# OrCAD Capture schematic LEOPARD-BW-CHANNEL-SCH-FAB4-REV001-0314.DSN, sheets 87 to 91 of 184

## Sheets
87 088_WBG - POWER: size A3; title: WBG - POWER
88 087_WBG - CLOCK: size A3; title: WBG - CLOCK
89 086_WBG - SPI: size A3; title: WBG - SPI
90 085_WBG - GPIO & SMB: size A3; title: WBG - GPIO & SMB
91 084_WBG - SATA: size A3; title: WBG - SATA

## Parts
sheet 083_WBG - DMI & USB
WBG1  WELLSBURG-1-GP-U  [BGA836M25H87]  (sections A,B,C,D,E,F,G,H,I,J,K)
sheet 084_WBG - SATA
C51  SCD1U16V2KX-3GP  [C402H22]
C52  SCD1U16V2KX-3GP  [C402H22]
C755  SCD01U16V2KX-3GP  [C402H22]
C756  SCD01U16V2KX-3GP  [C402H22]
L12  BLM15AG121SN-1GP  [L402H22]
R138  10KR2F-2-GP  [R402H16]
R139  10KR2F-2-GP  [R402H16]
R140  1KR2J-1-GP  [R402H16]
R141  7K5R2F-1-GP  [R402H16]
R203  10KR2F-2-GP  [R402H16]
R222  10KR2F-2-GP  [R402H16]
R230  10KR2F-2-GP  [R402H16]
R292  10KR2F-2-GP  [R402H16]
R296  2KR2F-3-GP  [R402H16]
R297  10KR2F-2-GP  [R402H16]
R298  10KR2F-2-GP  [R402H16]
R302  10KR2F-2-GP  [R402H16]
R322  10KR2F-2-GP  [R402H16]
R323  10KR2F-2-GP  [R402H16]
R353  10KR2F-2-GP  [R402H16]
R371  10KR2F-2-GP  [R402H16]
R522  10KR2F-2-GP  [R402H16]
R590  10KR2F-2-GP  [R402H16]
R611  10KR2F-2-GP  [R402H16]
R780  10KR2F-2-GP  [R402H16]
R831  10KR2F-2-GP  [R402H16]
R837  2KR2F-3-GP  [R402H16]
TP189  TPAD24  [TPAD24]
U43  74VHC1G09DFT2G-GP  [SC70-5H44]
U49  74VHC1G09DFT2G-GP  [SC70-5H44]
sheet 085_WBG - GPIO & SMB
C208  SC15P50V2JN-2-GP  [C402H22]
C209  SC15P50V2JN-2-GP  [C402H22]
R146  10KR2F-2-GP  [R402H16]
R151  10MR3J-L1-GP  [R603H22]
R170  4K7R2F-GP  [R402H16]
R171  4K7R2F-GP  [R402H16]
R172  4K7R2F-GP  [R402H16]
R173  4K7R2F-GP  [R402H16]
R174  10KR2F-2-GP  [R402H16]
R183  10KR2F-2-GP  [R402H16]
R185  2K2R2F-GP  [R402H16]
R186  10KR2F-2-GP  [R402H16]
R194  10KR2F-2-GP  [R402H16]
R196  10KR2F-2-GP  [R402H16]
R198  2K2R2F-GP  [R402H16]
R204  10KR2F-2-GP  [R402H16]
R283  10KR2F-2-GP  [R402H16]
R287  0R2J-2-GP  [R402H16]
R288  0R2J-2-GP  [R402H16]
R299  2K2R2F-GP  [R402H16]
R325  10KR2F-2-GP  [R402H16]
R364  10KR2F-2-GP  [R402H16]
R428  2K2R2F-GP  [R402H16]
R628  0R2J-2-GP  [R402H16]
R802  10KR2F-2-GP  [R402H16]
R853  10KR2F-2-GP  [R402H16]
R919  33R2F-3-GP  [R402H16]
R920  33R2F-3-GP  [R402H16]
R921  33R2F-3-GP  [R402H16]
R922  33R2F-3-GP  [R402H16]
R1046  0R2J-2-GP  [R402H16]
R1113  0R2J-2-GP  [R402H16]
R1114  0R2J-2-GP  [R402H16]
R1115  0R2J-2-GP  [R402H16]
R1585  0R2J-2-GP  [R402H16]
R1595  0R2J-2-GP  [R402H16]
R1597  0R2J-2-GP  [R402H16]
R1598  0R2J-2-GP  [R402H16]
TP192  TPAD24  [TPAD24]
TP193  TPAD24  [TPAD24]
TP199  TPAD24  [TPAD24]
TP234  TPAD24  [TPAD24]
TP235  TPAD24  [TPAD24]
TP236  TPAD24  [TPAD24]
TP334  TPAD24  [TPAD24]
TP335  TPAD24  [TPAD24]
TP336  TPAD24  [TPAD24]
TP337  TPAD24  [TPAD24]
TP338  TPAD24  [TPAD24]
TP339  TPAD24  [TPAD24]
TP340  TPAD24  [TPAD24]
TP341  TPAD24  [TPAD24]
TP343  TPAD24  [TPAD24]
TP351  TPAD24  [TPAD24]
X2  XTAL-32D768KHZ-63-GP  [SMD49-12H34]
sheet 086_WBG - SPI
R144  8K2R2F-1-GP  [R402H16]
R147  10KR2F-2-GP  [R402H16]
R390  10KR2F-2-GP  [R402H16]
TP237  TPAD24  [TPAD24]
sheet 087_WBG - CLOCK
C206  SC12P50V2JN-3GP  [C402H24]
C207  SC12P50V2JN-3GP  [C402H24]
R149  1KR2F-L-GP  [R402H16]
R150  1MR3F-GP  [R603H22]
R274  0R2J-2-GP  [R402H16]
R275  0R2J-2-GP  [R402H16]
R277  0R2J-2-GP  [R402H16]
R278  0R2J-2-GP  [R402H16]
R379  22R2F-1-GP  [R402H16]
R440  22D1R2F-GP  [R402H16]
R959  22D1R2F-GP  [R402H16]
R963  39R2F-GP  [R402H16]
TP327  TPAD24  [TPAD24]
X1  XTAL-25MHZ-96GP  [SMD49-4H56]
sheet 088_WBG - POWER
C210  SC10U6D3V5KX-4GP  [C805H58]
C211  SC1U10V2KX-4-GP  [C402H22]
C212  SC10U6D3V5KX-4GP  [C805H58]
C213  SC1U10V2KX-4-GP  [C402H22]
C214  SC10U6D3V5KX-4GP  [C805H58]
C215  SC10U6D3V5KX-4GP  [C805H58]
C216  SC1U10V2KX-4-GP  [C402H22]
C217  SC1U10V2KX-4-GP  [C402H22]
C218  SC10U6D3V5KX-4GP  [C805H58]
C219  SC1U10V2KX-4-GP  [C402H22]
C220  SC10U6D3V5KX-4GP  [C805H58]
C221  SC1U10V2KX-4-GP  [C402H22]
C662  SCD1U16V2KX-3GP  [C402H22]
L1  IND-10UH-215-GP  [L805H58]
L2  IND-1UH-109-GP  [L805H44]
L3  IND-10UH-215-GP  [L805H58]
L4  IND-1UH-109-GP  [L805H44]
L5  IND-10UH-215-GP  [L805H58]
L6  IND-10UH-215-GP  [L805H58]
L13  BLM15AG121SN-1GP  [L402H22]
R152  D001R2512-GP-U1  [R2512-1U1H36]
R153  D001R2512-GP-U1  [R2512-1U1H36]
R154  0R2J-2-GP  [R402H16]
R155  0R2J-2-GP  [R402H16]
R156  0R2J-2-GP  [R402H16]
R157  0R2J-2-GP  [R402H16]
R158  0R2J-2-GP  [R402H16]
R159  0R2J-2-GP  [R402H16]
R160  0R2J-2-GP  [R402H16]
R161  0R2J-2-GP  [R402H16]
R162  0R2J-2-GP  [R402H16]
R163  0R2J-2-GP  [R402H16]
R165  0R3J-0-U-GP  [R603H22]
R167  0R2J-2-GP  [R402H16]
R168  0R2J-2-GP  [R402H16]
R177  1R2J-GP  [R402H16]
R178  0R2J-2-GP  [R402H16]
TP278  TPAD24  [TPAD24]
TP329  TPAD24  [TPAD24]

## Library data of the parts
WBG1 = WELLSBURG-1-GP-U: IC PCH WELLSBURG FCBGA 836P(SERVER); GREENDFACTOR: R2_C;; POP?: 071.82029.0B0U; Package Type: ASIC2-G4; Part Number: 71.WSBUG.00U; SPEC: http://wpqssvr.wistron.com.tw:7001/wpqs/servlet/COM.qpart.Attachment?PartNumber=71.WSBUG.00U
C51 C52 = SCD1U16V2KX-3GP: CHIP CAP C 0.1U 16V K0402 X7R; CATEGORIES: CAP_1.xV; GREENDFACTOR: R2_SA;HF_SA;G_SA;; MAIN_SOURCE: M; Part Number: 78.10421.2FL; Part Type: SMD-BCG; SPEC: http://wpqssvr.wistron.com.tw:7001/wpqs/servlet/COM.qpart.Attachment?PartNumber=78.10421.2FL
C755 C756 = SCD01U16V2KX-3GP: CHIP CAP0.01U16V K0402 X7R(ROH; Category: PCH; Part Number: 78.10321.2FL; Part Type: SMD-BCG
L12 L13 = BLM15AG121SN-1GP: CHIP BAED BLM15AG121SN1D; GREENDFACTOR: R2_SA;HF_SA;G_SA;; Part Number: 68.00084.921; Part Type: DISCRET-G; SPEC: http://wpqssvr.wistron.com.tw:7001/wpqs/servlet/COM.qpart.Attachment?PartNumber=68.00084.921
R138 R139 R146 R147 R203 R222 R230 = 10KR2F-2-GP: CHIP RES 10K F 1/16W 0402; GREENDFACTOR: R2_SA;HF_SA;G_SA;; Part Number: 64.10025.6DL; Part Type: SMD-RG; SPEC: http://wpqssvr.wistron.com.tw:7001/wpqs/servlet/COM.qpart.Attachment?PartNumber=64.10025.6DL
R140 = 1KR2J-1-GP: CHIP RES 1K J 1/16W 0402; GREENDFACTOR: R2_SA;HF_SA;G_SA;; Part Number: 63.10234.1DL; Part Type: SMD-RG; SPEC: http://wpqssvr.wistron.com.tw:7001/wpqs/servlet/COM.qpart.Attachment?PartNumber=63.10234.1DL
R141 = 7K5R2F-1-GP: CHIP RES 7.5K F 1/16W 0402; Category: PCH; Part Number: 64.75015.6DL; Part Type: SMD-RG
R292 R297 R298 R302 R322 R390 R522 R590 R611 R780 R831 = 10KR2F-2-GP: CHIP RES 10K F 1/16W 0402; GREENDFACTOR: R2_SA;HF_SA;G_SA;; Package Type: SMD-RG; Part Number: 64.10025.6DL; SPEC: http://wpqssvr.wistron.com.tw:7001/wpqs/servlet/COM.qpart.Attachment?PartNumber=64.10025.6DL
R296 R837 = 2KR2F-3-GP: CHIP RES 2K F 1/16W 0402; Category: internal conn; DESCRIPTIO: CHIP RES 2K F 1/16W 0402; GREENDFACTOR: R2_SA;HF_SA;G_SA;; Package Type: SMD-RG; Part Number: 64.20015.6DL; Part Type: SMD-RG; SPEC: http://wpqssvr.wistron.com.tw:7001/wpqs/servlet/COM.qpart.Attachment?PartNumber=64.20015.6DL; VENDORPARTNUMBER: RM04FTN2001 / RTT022001FTH / RR0510S-202-FN / RC0402FR-072KL/WR04X2001FTL
R174 R183 R186 R194 R196 R283 R323 R325 R364 R802 = 10KR2F-2-GP: CHIP RES 10K F 1/16W 0402; Category: PCH; DESCRIPTIO: CHIP RES 10K F 1/16W 0402; GREENDFACTOR: R2_SA;HF_SA;G_SA;; Package Type: SMD-RG; Part Number: 64.10025.6DL; Part Type: SMD-RG; SPEC: http://wpqssvr.wistron.com.tw:7001/wpqs/servlet/COM.qpart.Attachment?PartNumber=64.10025.6DL; VENDORPARTNUMBER: RM04FTN1002 / RTT021002FTH / RR0510S-103-FN / RC0402FR-0710KL/WR04X1002FTL
R353 R371 = 10KR2F-2-GP: CHIP RES 10K F 1/16W 0402; GREENDFACTOR: R2_SA;HF_SA;G_SA;; POP?: NOPOP; Package Type: SMD-RG; Part Number: 64.10025.6DL; SPEC: http://wpqssvr.wistron.com.tw:7001/wpqs/servlet/COM.qpart.Attachment?PartNumber=64.10025.6DL
TP189 TP192 TP193 TP199 TP234-TP237 TP278 TP327 TP329 TP334-TP341 TP343 TP351 = TPAD24: 24 MILS TEST PAD; Category: PCH; Part Number: ZZ.PAD24.001; Part Type: DISCRET2
U43 U49 = 74VHC1G09DFT2G-GP: IC CMOS MC74VHC1G09DFT2G SC-70; CATEGORIES: Logic IC; GREENDFACTOR: R2_SA;HF_SA;G_SA;; MAIN_SOURCE: M; Part Number: 73.01G09.AAH; Part Type: DISCRET-G; SPEC: http://wpqssvr.wistron.com.tw:7001/wpqs/servlet/COM.qpart.Attachment?PartNumber=73.01G09.AAH
C208 C209 = SC15P50V2JN-2-GP: CHIP CAP C 15P 50V J0402 NPO; Category: PCH; DESCRIPTIO: CHIP CAP C 15P 50V J0402 NPO; GREENDFACTOR: R2_SA;HF_SA;G_SA;; MAIN_SOURCE: M; Package Type: SMD-BCG; Part Number: 78.15034.1FL; Part Type: SMD-BCG; SPEC: http://wpqssvr.wistron.com.tw:7001/wpqs/servlet/COM.qpart.Attachment?PartNumber=78.15034.1FL; VENDORPARTNUMBER: 04025A150JAT2A/C1005NPO150JGT/GRM1555C1H150JZ01D/223886915159/CL05C150JB5NNNC/UMK105CH150JV-F/0402N150J500LT
R151 = 10MR3J-L1-GP: CHIP RES 10M J 1/10W 0603; GREENDFACTOR: R2_SA;HF_SA;G_SA;; Package Type: SMD-RG; Part Number: 63.10633.15L; SPEC: http://wpqssvr.wistron.com.tw:7001/wpqs/servlet/COM.qpart.Attachment?PartNumber=63.10633.15L
R170 R171 = 4K7R2F-GP: CHIP RES 4.7K F 1/16W 0402; Category: CPU SIDE BAND; POP?: NOPOP; Part Number: 64.47015.6DL; Part Type: RCL_GP
R172 R173 = 4K7R2F-GP: CHIP RES 4.7K F 1/16W 0402; Category: CPU SIDE BAND; Part Number: 64.47015.6DL; Part Type: RCL_GP
R185 R198 R299 R428 = 2K2R2J-2-GP: CHIP RES 2.2K F 1/16W 0402; Category: BMC; DESCRIPTIO: CHIP RES 2.2K J 1/16W 0402; GREENDFACTOR: R2_SA;HF_SA;G_SA;; Package Type: RCL_GP; Part Number: 64.22015.6DL; Part Type: RCL_GP; SPEC: http://wpqssvr.wistron.com.tw:7001/wpqs/servlet/COM.qpart.Attachment?PartNumber=64.22015.6DL; VENDORPARTNUMBER: RM04FTN2201/RTT022201FTH/RR0510S-222-FN/RC0402FR-072K2L
R204 R853 = 10KR2F-2-GP: CHIP RES 10K F 1/16W 0402; Category: PCH; DESCRIPTIO: CHIP RES 10K F 1/16W 0402; GREENDFACTOR: R2_SA;HF_SA;G_SA;; POP?: NOPOP; Package Type: SMD-RG; Part Number: 64.10025.6DL; Part Type: SMD-RG; SPEC: http://wpqssvr.wistron.com.tw:7001/wpqs/servlet/COM.qpart.Attachment?PartNumber=64.10025.6DL; VENDORPARTNUMBER: RM04FTN1002 / RTT021002FTH / RR0510S-103-FN / RC0402FR-0710KL/WR04X1002FTL
R178 R274 R275 R277 R278 R287 R1046 = 0R2J-2-GP: CHIP RES 0 J 1/16W 0402; Category: PCH; DESCRIPTIO: CHIP RES 0 J 1/16W 0402; GREENDFACTOR: R2_SA;HF_SA;G_SA;; Package Type: SMD-RG; Part Number: 63.R0034.1DL; Part Type: SMD-RG; SPEC: http://wpqssvr.wistron.com.tw:7001/wpqs/servlet/COM.qpart.Attachment?PartNumber=63.R0034.1DL; VENDORPARTNUMBER: RM04JTN0/RTT02000JTH/RR0510X-000-XN/RC0402JR-070RL/WR04X000 PTL
R288 = 0R2J-2-GP: CHIP RES 0 J 1/16W 0402; Category: PCH; DESCRIPTIO: CHIP RES 0 J 1/16W 0402; GREENDFACTOR: R2_SA;HF_SA;G_SA;; POP?: NOPOP; Package Type: SMD-RG; Part Number: 63.R0034.1DL; Part Type: SMD-RG; SPEC: http://wpqssvr.wistron.com.tw:7001/wpqs/servlet/COM.qpart.Attachment?PartNumber=63.R0034.1DL; VENDORPARTNUMBER: RM04JTN0/RTT02000JTH/RR0510X-000-XN/RC0402JR-070RL/WR04X000 PTL
R154 R157 R159 R161 R163 R168 R628 R1113 R1114 = 0R2J-2-GP: CHIP RES 0 J 1/16W 0402; Category: BMC; DESCRIPTIO: CHIP RES 0 J 1/16W 0402; GREENDFACTOR: R2_SA;HF_SA;G_SA;; Package Type: SMD-RG; Part Number: 63.R0034.1DL; Part Type: SMD-RG; SPEC: http://wpqssvr.wistron.com.tw:7001/wpqs/servlet/COM.qpart.Attachment?PartNumber=63.R0034.1DL; VENDORPARTNUMBER: RM04JTN0/RTT02000JTH/RR0510X-000-XN/RC0402JR-070RL/WR04X000 PTL
R919-R922 = 33R2F-3-GP: CHIP RES 33 F 1/16W 0402(ROHS); Category: PCH; DESCRIPTIO: CHIP RES 33 F 1/16W 0402(ROHS); GREENDFACTOR: R2_SA;HF_SA;G_SA;; Package Type: SMD-RG; Part Number: 64.33R05.6DL; Part Type: SMD-RG; SPEC: http://wpqssvr.wistron.com.tw:7001/wpqs/servlet/COM.qpart.Attachment?PartNumber=64.33R05.6DL; VENDORPARTNUMBER: RM04FTN33R0/RTT0233R0FTH/RR0510S-330-FN/RC0402FR-0733RL/WR04X33R0FTL
R155 R156 R158 R160 R162 R167 R1115 = 0R2J-2-GP: CHIP RES 0 J 1/16W 0402; Category: BMC; DESCRIPTIO: CHIP RES 0 J 1/16W 0402; GREENDFACTOR: R2_SA;HF_SA;G_SA;; POP?: NOPOP; Package Type: SMD-RG; Part Number: 63.R0034.1DL; Part Type: SMD-RG; SPEC: http://wpqssvr.wistron.com.tw:7001/wpqs/servlet/COM.qpart.Attachment?PartNumber=63.R0034.1DL; VENDORPARTNUMBER: RM04JTN0/RTT02000JTH/RR0510X-000-XN/RC0402JR-070RL/WR04X000 PTL
R1585 R1595 = 0R2J-2-GP: CHIP RES 0 J 1/16W 0402; Category: Logic; DESCRIPTIO: CHIP RES 0 J 1/16W 0402; GREENDFACTOR: R2_SA;HF_SA;G_SA;; Package Type: SMD-RG; Part Number: 63.R0034.1DL; Part Type: SMD-RG; SPEC: http://wpqssvr.wistron.com.tw:7001/wpqs/servlet/COM.qpart.Attachment?PartNumber=63.R0034.1DL; VENDORPARTNUMBER: RM04JTN0/RTT02000JTH/RR0510X-000-XN/RC0402JR-070RL/WR04X000 PTL
R1597 R1598 = 0R2J-2-GP: CHIP RES 0 J 1/16W 0402; Category: Logic; DESCRIPTIO: CHIP RES 0 J 1/16W 0402; GREENDFACTOR: R2_SA;HF_SA;G_SA;; POP?: NOPOP; Package Type: SMD-RG; Part Number: 63.R0034.1DL; Part Type: SMD-RG; SPEC: http://wpqssvr.wistron.com.tw:7001/wpqs/servlet/COM.qpart.Attachment?PartNumber=63.R0034.1DL; VENDORPARTNUMBER: RM04JTN0/RTT02000JTH/RR0510X-000-XN/RC0402JR-070RL/WR04X000 PTL
X2 = XTAL-32D768KHZ-63-GP: XTAL 32.768KHZ 12.5P 20PPM 9H03200 SMD; GREENDFACTOR: R2_SA;HF_SA;; Package Type: DISCRET-G9; Part Number: 82.30001.F81; SPEC: http://wpqssvr.wistron.com.tw:7001/wpqs/servlet/COM.qpart.Attachment?PartNumber=82.30001.F81
R144 = 8K2R2F-1-GP: CHIP RES 8.2K F 1/16W0402(ROHS; GREENDFACTOR: R2_SA;HF_SA;G_SA;; Package Type: SMD-RG; Part Number: 64.82015.6DL; SPEC: http://wpqssvr.wistron.com.tw:7001/wpqs/servlet/COM.qpart.Attachment?PartNumber=64.82015.6DL
C206 C207 = SC12P50V2JN-3GP: CHIP CAP C 12P 50V J0402 NPO; CATEGORIES: CAP_Small; GREENDFACTOR: R2_SA;HF_SA;G_SA;; MAIN_SOURCE: M; Package Type: SMD-BCG; Part Number: 78.12034.1FL; SPEC: http://wpqssvr.wistron.com.tw:7001/wpqs/servlet/COM.qpart.Attachment?PartNumber=78.12034.1FL
R149 = 1KR2F-L-GP: CHIP RES 1K F 1/16W 0402; GREENDFACTOR: R2_SA;HF_SA;G_SA;; Part Number: 64.10015.L1L; Part Type: SMD-RG2; SPEC: http://wpqssvr.wistron.com.tw:7001/wpqs/servlet/COM.qpart.Attachment?PartNumber=64.10015.L1L
R150 = 1MR3F-GP: CHIP RES 1M F 1/10W 0603(ROHS); Category: PCH; Part Number: 64.10045.55L; Part Type: RCL_GP
R379 = 22R2F-1-GP: CHIP RES 22 F 1/16W 0402(ROHS); Category: Clock; DESCRIPTIO: CHIP RES 22 F 1/16W 0402(ROHS); GREENDFACTOR: R2_SA;HF_SA;G_SA;; Package Type: SMD-RG; Part Number: 64.22R05.6DL; Part Type: SMD-RG; SPEC: http://wpqssvr.wistron.com.tw:7001/wpqs/servlet/COM.qpart.Attachment?PartNumber=64.22R05.6DL; VENDORPARTNUMBER: RM04FTN22R0/RTT0222R0FTH/RR0510S-220-FN/RC0402FR-0722RL
R440 R959 = 22D1R2F-GP: CHIP RES 22.1 F 1/16W 0402; Category: PCH; Part Number: 64.22R15.6DL; Part Type: SMD-RG
R963 = 39R2F-GP: CHIP RES 39 F 1/16W 0402; GREENDFACTOR: R2_SA;HF_SA;G_SA;; POP?: NOPOP; Part Number: 64.39R05.6DL; Part Type: SMD-RG; SPEC: http://wpqssvr.wistron.com.tw:7001/wpqs/servlet/COM.qpart.Attachment?PartNumber=64.39R05.6DL
X1 = XTAL-25MHZ-96GP: XTAL 25MHZ 12P X5H025000FC1H-H; GREENDFACTOR: R2_SA;HF_SA;G_SA;; Package Type: DISCRET-G1; Part Number: 82.30020.791; SPEC: http://wpqssvr.wistron.com.tw:7001/wpqs/servlet/COM.qpart.Attachment?PartNumber=82.30020.791
C210 C212 C214 C215 C218 = SC10U6D3V5KX-4GP: CHIP CAP C 10U 6.3V K0805 X7R; GREENDFACTOR: R2_SA;HF_SA;G_SA;; Part Number: 78.10620.21L; Part Type: SMD-BCG; SPEC: http://wpqssvr.wistron.com.tw:7001/wpqs/servlet/COM.qpart.Attachment?PartNumber=78.10620.21L
C211 C213 C216 C217 C219 C221 = SC1U10V2KX-4-GP: CHIP CAP C 1U 10V K 0402 X6S; GREENDFACTOR: R2_SA;HF_SA;; Part Number: 78.10523.8FL; Part Type: SMD-BCG6; SPEC: http://wpqssvr.wistron.com.tw:7001/wpqs/servlet/COM.qpart.Attachment?PartNumber=78.10523.8FL
C220 = SC10U6D3V5KX-4GP: CHIP CAP C 10U 6.3V K0805 X7R; GREENDFACTOR: R2_SA;HF_SA;G_SA;; POP?: NOPOP; Part Number: 78.10620.21L; Part Type: SMD-BCG; SPEC: http://wpqssvr.wistron.com.tw:7001/wpqs/servlet/COM.qpart.Attachment?PartNumber=78.10620.21L
C662 = SCD1U16V2KX-3GP: CHIP CAP C 0.1U 16V K0402 X7R; Category: CLK GEN; GREENDFACTOR: R_SA;HF_SA;G_SA;; Part Number: 78.10421.2FL; Quotation: 12_14; Type: SMD
L1 L3 L5 = IND-10UH-215-GP: CHIP IND 10UH CL201212T-100M-M; Category: PCH; Part Number: 68.1001D.10E; Part Type: DISCRET-G6
L2 L4 = IND-1UH-109-GP: CHIP IND 1U K CL201209T-1R0K-N; Category: PCH; Part Number: 68.1R020.1N1; Part Type: DISCRET-G6
L6 = IND-10UH-215-GP: CHIP IND 10UH CL201212T-100M-M; Category: PCH; POP?: NOPOP; Part Number: 68.1001D.10E; Part Type: DISCRET-G6
R152 = D001R2512-GP-U1: CHIP RES 0.001 F 1W 2512; GREENDFACTOR: R2_SA;HF_SA;G_SA;; POP?: NOPOP; Package Type: SMD-RG6; Part Number: 64.R0015.77L; SPEC: http://wpqssvr.wistron.com.tw:7001/wpqs/servlet/COM.qpart.Attachment?PartNumber=64.R0015.77L
R153 = D001R2512-GP-U1: CHIP RES 0.001 F 1W 2512; GREENDFACTOR: R2_SA;HF_SA;G_SA;; Package Type: SMD-RG6; Part Number: 64.R0015.77L; SPEC: http://wpqssvr.wistron.com.tw:7001/wpqs/servlet/COM.qpart.Attachment?PartNumber=64.R0015.77L
R165 = 0R3J-0-U-GP: CHIP RES 0 J 1/10W 0603; GREENDFACTOR: R2_SA;HF_SA;G_SA;; Package Type: RCL_GP; Part Number: 63.00000.00L; SPEC: http://wpqssvr.wistron.com.tw:7001/wpqs/servlet/COM.qpart.Attachment?PartNumber=63.00000.00L
R177 = 1R2J-GP: CHIP RES 1 J 1/16W 0402; Category: PCH; Part Number: 63.1R034.1DL; Part Type: RCL_GP

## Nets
GND: C51.2 C52.2 C206.2 C207.2 C208.2 C209.2 C210.2 C211.2 C212.2 C213.2 C214.2 C215.2 C216.2 C217.2 C218.2 C219.2 C220.2 C221.2 C662.2 R140.1 R144.1 R230.2 R390.2 U43.3(GND) U49.3(GND) ; also on sheet 1 2 3 4 5 6 7 8 9 10 11 12 13 14 15 16 17 18 19 20 21 22 23 24 25 26 27 28 29 30 31 32 33 34 35 36 37 38 39 44 46 47 49 50 51 52 53 54 55 56 57 58 59 60 61 62 63 64 65 66 69 70 71 73 74 75 76 78 79 80 81 82 83 84 86 92 93 94 95 96 97 98 99 100 101 102 103 104 105 106 107 108 109 110 111 112 113 114 115 116 117 118 119 128 129 138 139 159 160 161 166 168 169 170 171 172 173 174 175 176 177 180 181 182 183 184
P1V05_DMI_PLL: C212.1 C213.1 L2.2(S) R156.2
P1V05_DSW_INT_CAP: WBG1.N29(DCPSUSBYP) ; also on sheet 173
P1V05_ME_PWR_OPTION: R152.2 R153.2 WBG1.AA26(VCCASW) WBG1.AA27(VCCASW) WBG1.AA29(VCCASW) WBG1.AC26(VCCASW) WBG1.AC27(VCCASW) WBG1.AC29(VCCASW) WBG1.J27(VCCASW) WBG1.T27(VCCASW) WBG1.V26(VCCASW) WBG1.V27(VCCASW) WBG1.V29(VCCASW) WBG1.W29(VCCASW) ; also on sheet 173
P1V5_PCH: L12.2 R157.2 R159.2 R161.2 R163.2 R168.2 WBG1.AP18(VCCVRM) WBG1.AP19(VCCVRM) ; also on sheet 8 45 166 173
P1V05_PCH: L1.1(F) L2.1(F) L3.1(F) L4.1(F) L5.1(F) L6.1(F) R152.1 R155.2 WBG1.AA12(VCCIO) WBG1.AA18(VCCIO) WBG1.AA19(VCCIO) WBG1.AA21(VCC) WBG1.AA23(VCC) WBG1.AA24(VCC) WBG1.AC21(VCC) WBG1.AC23(VCC) WBG1.AC24(VCC) WBG1.AC31(VCC) WBG1.AF21(VCC) WBG1.AF23(VCC) WBG1.AF24(VCC) WBG1.AF26(VCC) WBG1.AF27(VCC) WBG1.AF29(VCC) WBG1.AF31(VCC) WBG1.AG18(VCCIO) WBG1.AG19(VCCIO) WBG1.AG21(VCC) WBG1.AG23(VCC) WBG1.AG24(VCC) WBG1.AG26(VCC) WBG1.AG27(VCC) WBG1.AG29(VCCAUSBPLL) WBG1.AG31(VCC) WBG1.AJ18(VCCIO) WBG1.AJ29(VCCAUSBPLL) WBG1.AL18(VCC) WBG1.AL19(VCC) WBG1.AL21(VCCCLK) WBG1.AL23(VCCCLK) WBG1.AL24(VCC) WBG1.AL26(VCC) WBG1.AL27(VCC) WBG1.AL29(VCC) WBG1.AL31(VCC) WBG1.AL32(VCC) WBG1.AM23(VCCCLK) WBG1.AM24(VCCCLK) WBG1.AM26(VCCCLK) WBG1.AP21(VCCCLK) WBG1.AP23(VCCCLK) WBG1.AP24(VCCCLK) WBG1.AU21(VCCCLK) WBG1.AU23(VCCCLK) WBG1.AW34(VCC) WBG1.N12(VCCIO) WBG1.T18(VCCIO) WBG1.T19(VCCIO) WBG1.T21(VCC) WBG1.T23(VCC) WBG1.V9(VCCIO) WBG1.V18(VCCIO) WBG1.V19(VCCIO) WBG1.V21(VCC) WBG1.V23(VCC) WBG1.W21(VCC) ; also on sheet 10 45 173 175
P1V05_SATA3_PLL: C215.1 C217.1 L3.2(S) R158.2
P1V05_SATA3X_PLL: C220.1 L6.2(S) R167.2
P1V05_STBY_PCH: R153.1 WBG1.V31(VCCASW) WBG1.V32(VCCASW) WBG1.Y35(VCCASW) ; also on sheet 9 45 76
P1V05_SUS_INT_CAP: WBG1.T29(DCPSUS1) ; also on sheet 175
P1V05_USB3_PLL: C214.1 C216.1 L4.2(S) R160.2
P1V5_VCCSST_INT_CAP: WBG1.N27(DCPSST) ; also on sheet 173
P1V05_XCK_DCB: C218.1 C219.1 R154.2 R178.2
P1V05_XCK_VRM: C210.1 C211.1 R162.2 R177.2
P1V05_XCK_VRM_L: L1.2(S) R177.1
P3V3: L13.1 R138.1 R139.1 R165.2 R174.1 R203.2 R222.2 R292.2 R296.1 R297.2 R298.2 R299.1 R302.2 R322.2 R323.1 R353.2 R371.2 R522.1 R780.2 R802.1 R831.2 R837.1 R853.1 WBG1.AJ15(VCCST3_3) WBG1.AP32(VCC3_3) WBG1.AT46(VCCST3_3) WBG1.J25(VCC3_3) WBG1.T24(VCC3_3) WBG1.V24(VCC3_3) ; also on sheet 1 3 8 45 46 48 49 52 54 58 65 74 76 78 83 84 94 95 96 100 101 102 161 166 168 173 174 177 180 181 182 183
P3V3_STBY: C51.1 C52.1 C662.1 R146.1 R147.2 R149.1 R170.1 R171.1 R172.1 R173.1 R183.1 R185.1 R186.1 R194.1 R196.1 R198.2 R204.1 R283.1 R325.1 R364.1 R428.1 R590.1 R611.1 U43.5(VCC) U49.5(VCC) WBG1.AA31(VCCSUS3_3) WBG1.AA32(VCCSUS3_3) WBG1.AC18(VCCSUS3_3) WBG1.AC19(VCCSUS3_3) WBG1.AC32(VCCSUS3_3) WBG1.AF32(VCCSUS3_3) WBG1.AG32(VCCSUS3_3) WBG1.AG38(VCCSUSHDA) WBG1.AJ32(VCCSUS3_3) WBG1.T26(VCCSPI) WBG1.T32(VCCDSW3_3) WBG1.T35(VCCSUS3_3) ; also on sheet 2 3 5 6 8 9 10 11 12 15 16 17 20 21 22 25 26 27 30 31 33 34 35 37 38 39 45 47 49 50 51 52 54 55 59 60 61 62 63 64 65 66 69 70 71 72 73 74 76 79 83 84 92 93 94 95 96 97 98 99 159 161 166 168 173 174 176 177 179 180 182 183 184
P3V_BAT: WBG1.N38(VCCRTC) ; also on sheet 84 173 174 184
PVCCIO: WBG1.AP26(V_PROC_IO) WBG1.L18(V_PROC_IO) ; also on sheet 11 16 26 35 39 46 47 68 97 100 101 102 103 120 129 130 139 160 173 177 179 182
VCCA_DMI_PLL_PCH: R156.1 R157.1 WBG1.AA9(VCCVRM)
VCCA_SATA3_PLL_PCH: R158.1 R159.1 WBG1.N9(VCCVRM)
VCCA_SATA3X_PLL_PCH: C221.1 R167.1 R168.1 WBG1.AP36(VCCVRM)
VCCA_USB3_PLL_PCH: R160.1 R161.1 WBG1.AC15(VCCVRM)
VCCAXCK_DCB_PCH: R154.1 R155.1 WBG1.AU18(VCCCLK)
VCCAXCK_VRM_1P5_PCH: R162.1 R163.1 WBG1.AU15(VCCVRM)
VCCCLK3_3: L13.2 WBG1.AP27(VCCCLK3_3) WBG1.AP29(VCCCLK3_3) WBG1.AU27(VCCCLK3_3) WBG1.AU29(VCCCLK3_3) WBG1.AU32(VCCCLK3_3) WBG1.AV27(VCCCLK3_3) WBG1.AV29(VCCCLK3_3) WBG1.AV32(VCCCLK3_3) ; also on sheet 175
AUD_AZA_SDO: WBG1.AR47(HDA_SDO) ; also on sheet 174
BIOS_FW_GD_N: R325.2 WBG1.G39(GPIO25) ; also on sheet 180
BOARD_ID1_PCH: WBG1.B36(GPIO24/MGPIO0) ; also on sheet 71
BOARD_ID3_PCH: WBG1.M27(GPIO28/MGPIO7) ; also on sheet 71
CLK_14M_PCH: R390.1 WBG1.BA23(REFCLK14IN)
CLK_33K_SUSCLK_PLD: WBG1.J32(SUSCLK/GPIO62) ; also on sheet 50 174
CLK_33M_BMC1_LPC: R959.2 ; also on sheet 74
CLK_33M_CPLD_LPC: R963.2 ; also on sheet 52
CLK_33M_PCH: R379.2 ; also on sheet 166
CLK_33M_PCH_BMC_LPC_R: R959.1 WBG1.BF22(CLKOUT_PCI2)
CLK_33M_PCH_CPLD_R: R963.1 WBG1.BF24(CLKOUT_PCI4)
CLK_33M_PCH_TPM_CONN_R: R440.1 WBG1.BH24(CLKOUT_PCI3)
CLK_33M_PCH_TPM_R: R379.1 WBG1.BH22(CLKOUT_PCI0)
CLK_33M_TPM_CONN: R440.2 ; also on sheet 78
CLK_100M_DB1900_DN: R275.2 ; also on sheet 58
CLK_100M_DB1900_DP: R274.2 ; also on sheet 58
CLK_100M_PCH_CPY_DN: WBG1.P2(CLKIN_CPY_N) ; also on sheet 56
CLK_100M_PCH_CPY_DP: WBG1.P4(CLKIN_CPY_P) ; also on sheet 56
CLK_100M_PCH_DB1900_R_DN: R275.1 WBG1.AY4(CLKOUT_DMI_N1)
CLK_100M_PCH_DB1900_R_DP: R274.1 WBG1.AY2(CLKOUT_DMI_P1)
CLK_100M_PCH_XDP_DN: R278.1 WBG1.BC16(CLKOUT_ITPXDP_N)
CLK_100M_PCH_XDP_DP: R277.1 WBG1.BD16(CLKOUT_ITPXDP_P)
CLK_100M_XDP_DN: R278.2 ; also on sheet 47
CLK_100M_XDP_DP: R277.2 ; also on sheet 47
COM1_RI_BMC: R1046.2 ; also on sheet 180
DB_PRESENT_N: R628.2 ; also on sheet 69
DB_PRESENT_R_N: R174.2 R628.1 WBG1.A25(BMBUSY#/GPIO0)
FILTER_P1V05_XCK_DCB: L5.2(S) R178.1
FM_BIOS_POST_CMPLT_N: R283.2 WBG1.D34(GPIO46) ; also on sheet 74
FM_BIOS_RCVR_BOOT_N: WBG1.G27(GPIO45) ; also on sheet 84
FM_BMC_PCH_SCI_LPC_N: R194.2 WBG1.AM48(GPIO13) ; also on sheet 74
FM_BMC_PWRBTN_OUT_N: WBG1.N43(PWRBTN#) ; also on sheet 168
FM_GPIO_ALERT_BUF_EN: R230.1 WBG1.V36(TACH7/GPIO71) ; also on sheet 52
FM_LA_TRIGGER_N_PLD_TDO: WBG1.J29(GPIO26) ; also on sheet 84
FM_LVC1_THERMTRIP_N: WBG1.A13(THRMTRIP#) ; also on sheet 182
FM_ME_CMM_N: R1115.2 ; also on sheet 84
FM_ME_RCVR_N: WBG1.C39(GPIO57/MGPIO5) ; also on sheet 84
FM_MEZZ_PRSNT_N: R802.2 WBG1.J21(GPIO32) ; also on sheet 95
FM_NMI_EVENT_N_NOA_CLK2: WBG1.F11(GPIO35/NMI#) ; also on sheet 180
FM_PASSWORD_CLEAR_N: WBG1.N44(INTRUDER#) ; also on sheet 84
FM_PCH_BMC_THERMTRIP_N: R1114.2 ; also on sheet 52
FM_PCH_BMC_THERMTRIP_R_N: R198.1 R1114.1 R1115.1 WBG1.L44(SML1ALERT#/PCHHOT#/GPIO74/MGPIO8)
FM_PCH_LAN1_DISABLE_N: WBG1.G32(GPIO44) ; also on sheet 64 174
FM_PCH_LDRQ_N: TP343.1 WBG1.AD46(LDRQ0#)
FM_PCH_PRSNT_CO_N: R147.1 WBG1.D48(CGC_DUT_DETECT#) ; also on sheet 51
FM_PCIE_SLOT_CPRSNT2_N: WBG1.V44(TACH2/GPIO6) ; also on sheet 94
FM_PCIE_SLOT_CPRSNT3_N: WBG1.AW23(CLKOUTFLEX0/GPIO64) ; also on sheet 94
FM_PCIE_SLOT_CPRSNT4_N: WBG1.BC23(CLKOUTFLEX3/GPIO67) ; also on sheet 94
FM_PCIE_SLOT_CPRSNT5_N: WBG1.BJ17(CLKOUTFLEX2/GPIO66) ; also on sheet 94
FM_PCIE_SLOT_CPRSNT6_N: WBG1.BD23(CLKOUTFLEX1/GPIO65) ; also on sheet 94
FM_QPI_SLOW_MODE_N: WBG1.AJ49(GPIO33) ; also on sheet 84
FM_SLPA_N: WBG1.E48(SLP_A#) ; also on sheet 9
FM_SLPS3_N: WBG1.B46(SLP_S3#) ; also on sheet 51 52 59 74
FM_SLPS4_N: WBG1.J49(SLP_S4#) ; also on sheet 51 74
FM_SMI_ACTIVE_N: WBG1.M23(GPIO20/SMI#) ; also on sheet 74
FM_USB3_P0_EN_N: R353.1 WBG1.V41(TACH6/GPIO70) ; also on sheet 176
FM_USB3_P1_EN_N: R371.1 WBG1.T40(TACH0/GPIO17) ; also on sheet 176
H_PM_SYNC_G: WBG1.J18(PM_SYNC) ; also on sheet 129 139
HDD_LED_SATA_ACT_N: U43.4(OUT_Y) U49.4(OUT_Y) ; also on sheet 65
IRQ_BMC_PCH_NMI_NOA1_CLK_MUX: WBG1.C41(GPIO8) ; also on sheet 174
IRQ_IBMC_PCH_SMI_LPC_N: R364.2 WBG1.L47(LAN_PHY_PWR_CTRL/GPIO12) ; also on sheet 177
IRQ_LVC3_WAKE_N: R149.2 WBG1.F44(WAKE#) ; also on sheet 64 74 81 83 94 95 168
IRQ_SERIAL: R323.2 WBG1.L21(SERIRQ) ; also on sheet 52 74 78
IRQ_SML0_ALERT_N: R1113.2 ; also on sheet 74
IRQ_SML0_ALERT_R_N: R1113.1 WBG1.D42(SML0ALERT#/GPIO60/MGPIO4)
IRQ_SML1_PMBUS_ALERT_N: R204.2 WBG1.K48(GPIO31/MGPIO2) ; also on sheet 52 54 60 74
LED_SATA_ACT_N: R222.1 U49.1(IN_B) WBG1.J7(SATALED#)
LED_SSATA_ACT_N: R203.1 U49.2(IN_A) WBG1.BH34(SSATALED#)
LPC_FRAME_N: WBG1.AA41(LFRAME#) ; also on sheet 52 74 78
LPC_LAD0: R922.1 ; also on sheet 74 78
LPC_LAD1: R921.1 ; also on sheet 74 78
LPC_LAD2: R920.1 ; also on sheet 74 78
LPC_LAD3: R919.1 ; also on sheet 74 78
MSATA_LED_N: R590.2 U43.1(IN_B) ; also on sheet 81
MSATA_SSD_PRSNT_N: R522.2 WBG1.T36(TACH4/GPIO68) ; also on sheet 81
NGFF_LED_N: R611.2 U43.2(IN_A) ; also on sheet 83
NOA_8_GP21_PD: WBG1.D4(SATA0GP/GPIO21) ; also on sheet 174
NOA_9_RST_PCIE_PCH_N: WBG1.B24(SATA1GP/GPIO19) ; also on sheet 48 49
NOA_10_FM_BIOS_ADV_FUNCTIONS: WBG1.B5(SATA2GP/GPIO36) ; also on sheet 174
NOA_12_FM_NM_THROTTLE_N: WBG1.A9(SATA4GP/GPIO16/MGPIO9) ; also on sheet 183
NOA_13_FM_CPU_PROCHOT_N: WBG1.B28(SATA5GP/GPIO49/MGPIO10) ; also on sheet 48
NOA_14_GP18_TP: WBG1.G21(GPIO18) ; also on sheet 48
PCH_DIMM_RDY: R322.1 WBG1.T38(TACH3/GPIO7) ; also on sheet 52
PCH_LPC_LAD0: R922.2 WBG1.AA40(LAD0)
PCH_LPC_LAD1: R921.2 WBG1.AA38(LAD1)
PCH_LPC_LAD2: R920.2 WBG1.AC47(LAD2)
PCH_LPC_LAD3: R919.2 WBG1.AA36(LAD3)
PCH_VCCPFUSE_3P3_R: R165.1 WBG1.T31(VCC3_3) ; also on sheet 173
PCH_XCLK_BIASREF: L12.1 R141.2 WBG1.AW11(ICLK_IREF)
PCH_XCLK_BIASREF_R: R141.1 WBG1.BA11(DIFFCLK_BIASREF)
PD_PCH_SSTCTL: R140.2 WBG1.C43(SST)
PD_PGDMON: WBG1.AH46(NCTF/TP#AH46) ; also on sheet 174
PD_TD_IREF: R144.2 WBG1.BC6(TD_IREF)
PECI_PCH: WBG1.A21(PECI) ; also on sheet 68
POWER_FAIL: WBG1.G11(SATA3GP/GPIO37) ; also on sheet 54 60
PU_GPIO15_SSB: R428.2 WBG1.B34(GPIO15)
PU_PCH_DSWODVREN: WBG1.N40(DSWVRMEN) ; also on sheet 174
PU_PCH_GP73_PLD_TMS: R183.2 WBG1.F29(GPIO73)
PU_PCH_GPIO1: R831.1 WBG1.T41(TACH1/GPIO1)
PU_PCH_GPIO34: R299.2 WBG1.F21(GPIO34)
PU_PCH_GPIO72: R186.2 WBG1.G47(GPIO72)
PU_PCH_INTVRMEN: WBG1.N47(INTVRMEN) ; also on sheet 174
PU_PCH_RCIN_N: R139.2 WBG1.C25(RCIN#)
PU_PCH_RI_R_N: R185.2 R1046.1 WBG1.J39(RI#)
PU_PCH_RSVD_6: R138.2 WBG1.B26(RESERVED#B26)
PU_SATAX0GP: R292.1 WBG1.AW32(SSATA0GP)
PU_SATAX1GP: R302.1 WBG1.BF36(SSATA1GP)
PU_SATAX2GP: R298.1 WBG1.BH36(SSATA2GP)
PU_SATAX3GP: R297.1 WBG1.BF38(SSATA3GP)
PU_SGPIO_SATA_DATAOUT1: R837.2 WBG1.D6(SDATAOUT1/GPIO48)
PU_SUSACK_N: R146.2 WBG1.A41(SUSACK#)
PWRGD_CPUPWRGD_1V: WBG1.F6(PROCPWRGD) ; also on sheet 182
PWRGD_DRAMPWRGD_CO: R196.2 WBG1.B45(DRAMPWROK) ; also on sheet 97
PWRGD_P1V05_PCH_STBY_DLY: R287.2 ; also on sheet 51 174
PWRGD_PCH_APWROK: R287.1 R288.2 WBG1.G29(APWROK)
PWRGD_PCH_PWROK: R288.1 WBG1.M48(PCH_PWROK) ; also on sheet 51 52 174
PWRGD_SYS_PWROK: WBG1.D30(SYS_PWROK) ; also on sheet 51 52 174
REVISION_ID0_PCH: WBG1.L29(GPIO27/MGPIO6) ; also on sheet 71
REVISION_ID1_PCH: WBG1.H48(SLP_WLAN#/GPIO29/MGPIO3) ; also on sheet 71
REVISION_ID2_PCH: WBG1.F43(SUSWARN#/GPIO30/MGPIO1) ; also on sheet 71
ROW_EN: R853.2 WBG1.AA35(LDRQ1#/GPIO23) ; also on sheet 168
RST_PCH_RSTBTN_N: WBG1.D26(SYS_RESET#) ; also on sheet 182
RST_PCIE_CPU_N: WBG1.F39(SMBALERT#/GPIO11) ; also on sheet 51
RST_PLTRST_N: WBG1.G38(PLTRST#) ; also on sheet 51 100 174 177
RST_RSMRST_PCH_N: WBG1.N41(DPWROK) WBG1.T44(RSMRST#) ; also on sheet 182
RST_RTCRST_N: WBG1.P48(RTCRST#) ; also on sheet 84
RST_SRTCRST_N: WBG1.M46(SRTCRST#) ; also on sheet 84
SATA0_TX_C_DN: WBG1.B12(SATA_TXN0) ; also on sheet 1
SATA0_TX_C_DP: WBG1.D12(SATA_TXP0) ; also on sheet 1
SATA1_TX_C_DN: WBG1.D14(SATA_TXN1) ; also on sheet 1
SATA1_TX_C_DP: WBG1.B14(SATA_TXP1) ; also on sheet 1
SATA2_TX_C_DN: WBG1.B16(SATA_TXN2) ; also on sheet 1
SATA2_TX_C_DP: WBG1.D16(SATA_TXP2) ; also on sheet 1
SATA3_TX_C_DN: WBG1.B18(SATA_TXN3) ; also on sheet 1
SATA3_TX_C_DP: WBG1.D18(SATA_TXP3) ; also on sheet 1
SATA4_TX_C_DN: C756.2 WBG1.B8(SATA_TXN4/PETN1)
SATA4_TX_C_DP: C755.2 WBG1.D8(SATA_TXP4/PETP1)
SATA4_TX_DN: C756.1 ; also on sheet 81 83
SATA4_TX_DP: C755.1 ; also on sheet 81 83
SATA5_TX_C_DN: WBG1.D10(SATA_TXN5/PETN2) ; also on sheet 82
SATA5_TX_C_DP: WBG1.B10(SATA_TXP5/PETP2) ; also on sheet 82
SATA6G_P0_RX_DN: WBG1.G12(SATA_RXN0) ; also on sheet 1
SATA6G_P0_RX_DP: WBG1.F12(SATA_RXP0) ; also on sheet 1
SATA6G_P1_RX_DN: WBG1.J16(SATA_RXN1) ; also on sheet 1
SATA6G_P1_RX_DP: WBG1.L16(SATA_RXP1) ; also on sheet 1
SATA6G_P2_RX_DN: WBG1.N18(SATA_RXN2) ; also on sheet 1
SATA6G_P2_RX_DP: WBG1.M18(SATA_RXP2) ; also on sheet 1
SATA6G_P3_RX_DN: WBG1.F18(SATA_RXN3) ; also on sheet 1
SATA6G_P3_RX_DP: WBG1.G18(SATA_RXP3) ; also on sheet 1
SATA6G_P4_RX_DN: WBG1.F7(SATA_RXN4/PERP1) ; also on sheet 81 83
SATA6G_P4_RX_DP: WBG1.G7(SATA_RXP4/PERN1) ; also on sheet 81 83
SATA6G_P5_RX_DN: WBG1.J11(SATA_RXN5/PERP2) ; also on sheet 82
SATA6G_P5_RX_DP: WBG1.L11(SATA_RXP5/PERN2) ; also on sheet 82
SGPIO_SATA_CLOCK: WBG1.J12(SCLOCK/GPIO22) ; also on sheet 1
SGPIO_SATA_DATAOUT0: WBG1.M21(SDATAOUT0/GPIO39) ; also on sheet 1
SGPIO_SATA_LOAD: WBG1.G6(SLOAD/GPIO38) ; also on sheet 1
SGPIO_SSATA_CLOCK: WBG1.BD29(SSCLOCK) ; also on sheet 1
SGPIO_SSATA_DATAOUT0: WBG1.BH38(SSDATAOUT0) ; also on sheet 1
SGPIO_SSATA_LOAD: WBG1.BC29(SSLOAD) ; also on sheet 1
SMB_CLK: R170.2 R1585.2 WBG1.L39(SMBCLK)
SMB_DATA: R171.2 R1595.2 WBG1.B40(SMBDATA)
SMB_HOST_STBY_LVC3_CLK: R1585.1 ; also on sheet 47 55 74 77 161
SMB_HOST_STBY_LVC3_DATA: R1595.1 ; also on sheet 47 55 74 77 161
SMB_PMBUS_BMC_STBY_LVC3_CLK: R1597.1 ; also on sheet 60 74 77 162
SMB_PMBUS_BMC_STBY_LVC3_DATA: R1598.1 ; also on sheet 60 74 77 162
SMB_SMLINK0_STBY_LVC3_CLK: WBG1.J38(SML0CLK) ; also on sheet 74 77
SMB_SMLINK0_STBY_LVC3_DATA: WBG1.F38(SML0DATA) ; also on sheet 74 77
SML1_CLK: R172.2 R1597.2 WBG1.L38(SML1CLK/GPIO58/MGPIO11)
SML1_DATA: R173.2 R1598.2 WBG1.N36(SML1DATA/GPIO75/MGPIO12)
SPEAKER_PCH: WBG1.C27(SPKR) ; also on sheet 65 174
SPI_PCH_CLK_R: WBG1.C31(SPI_CLK) ; also on sheet 79
SPI_PCH_CS0_R_N: WBG1.G23(SPI_CS0#) ; also on sheet 79
SPI_PCH_IO2_R: WBG1.L27(SPI_IO2) ; also on sheet 79
SPI_PCH_IO3_R: WBG1.C29(SPI_IO3) ; also on sheet 79
SPI_PCH_MISO_R: WBG1.N23(SPI_MISO) ; also on sheet 79
SPI_PCH_MOSI_R: WBG1.B30(SPI_MOSI) ; also on sheet 79
SSATA6G_0_RX_C_DN: WBG1.AU44(SSATA_RXN0) ; also on sheet 1
SSATA6G_0_RX_C_DP: WBG1.AU43(SSATA_RXP0) ; also on sheet 1
SSATA6G_0_TX_C_DN: WBG1.BB46(SSATA_TXN0) ; also on sheet 1
SSATA6G_0_TX_C_DP: WBG1.BB48(SSATA_TXP0) ; also on sheet 1
SSATA6G_1_RX_C_DN: WBG1.AW44(SSATA_RXN1) ; also on sheet 1
SSATA6G_1_RX_C_DP: WBG1.BA44(SSATA_RXP1) ; also on sheet 1
SSATA6G_1_TX_C_DN: WBG1.BE48(SSATA_TXN1) ; also on sheet 1
SSATA6G_1_TX_C_DP: WBG1.BD46(SSATA_TXP1) ; also on sheet 1
SSATA6G_2_RX_C_DN: WBG1.BD43(SSATA_RXN2) ; also on sheet 1
SSATA6G_2_RX_C_DP: WBG1.BC43(SSATA_RXP2) ; also on sheet 1
SSATA6G_2_TX_C_DN: WBG1.BH42(SSATA_TXN2) ; also on sheet 1
SSATA6G_2_TX_C_DP: WBG1.BF42(SSATA_TXP2) ; also on sheet 1
SSATA6G_3_RX_C_DN: WBG1.BA39(SSATA_RXN3) ; also on sheet 1
SSATA6G_3_RX_C_DP: WBG1.AW39(SSATA_RXP3) ; also on sheet 1
SSATA6G_3_TX_C_DN: WBG1.BH40(SSATA_TXN3) ; also on sheet 1
SSATA6G_3_TX_C_DP: WBG1.BF40(SSATA_TXP3) ; also on sheet 1
SUS_STAT_N_PLD_TDI: TP193.1 WBG1.C37(GPIO61)
TP_CLKOUT_PCI_1: TP327.1 WBG1.BJ21(CLKOUT_PCI1)
TP_PCH_HDA_BCLK: TP340.1 WBG1.AK48(HDA_BCLK)
TP_PCH_HDA_RST_N: TP341.1 WBG1.AM46(HDA_RST#)
TP_PCH_HDA_SDI0: TP339.1 WBG1.AJ47(HDA_SDI0)
TP_PCH_HDA_SDI1: TP338.1 WBG1.AL47(HDA_SDI1)
TP_PCH_HDA_SDI2: TP337.1 WBG1.AN49(HDA_SDI2)
TP_PCH_HDA_SDI3: TP336.1 WBG1.AN47(HDA_SDI3)
TP_PCH_HDA_SYNC: TP351.1 WBG1.AP48(HDA_SYNC)
TP_PCH_PMTEST_RST: TP236.1 WBG1.A33(NCTF/TP#A33)
TP_PCH_RSVD_4: TP192.1 WBG1.F34(RESERVED#F34)
TP_PM_SYNC2: TP189.1 WBG1.BJ27(PM_SYNC2)
TP_RST_PLTRST_CPU_1V05_N: TP237.1 WBG1.A17(PLTRST_PROC#)
TP_SGPIO_SATAX_DATAOUT1: R296.2 WBG1.BF34(SSDATAOUT1)
TP_SLP_LAN_N: TP235.1 WBG1.J47(SLP_LAN#)
TP_SLPS5_N: TP199.1 WBG1.D38(SLP_S5#/GPIO63)
TP_SLPSUS_N_BUFF: TP234.1 WBG1.H46(SLP_SUS#)
TP_SPI_CS1: TP335.1 WBG1.L23(SPI_CS1#)
TP_SPI_CS2: TP334.1 WBG1.N21(SPI_CS2#)
TP_VCCDUSBSUS_1P05: TP278.1 WBG1.AC35(DCPSUS2)
TP_VCCUSB3SUS_1P05: TP329.1 WBG1.AF18(DCPSUS3) WBG1.AF19(DCPSUS3)
TPM_PRSNT_N: R780.1 WBG1.T43(TACH5/GPIO69) ; also on sheet 78
XDP_PCH_TCK0: WBG1.G34(JTAG_TCK) ; also on sheet 49
XDP_PCH_TDI: WBG1.F32(JTAG_TDI) ; also on sheet 49
XDP_PCH_TDO: WBG1.C33(JTAG_TDO) ; also on sheet 49
XDP_PCH_TMS: WBG1.B32(JTAG_TMS) ; also on sheet 49
XTAL_PCH_25M_IN: C206.1 R150.1 WBG1.BA12(XTAL25_IN) X1.1
XTAL_PCH_25M_OUT: C207.1 R150.2 WBG1.AW12(XTAL25_OUT) X1.2
XTAL_PCH_RTC1: C209.1 R151.1 WBG1.T46(RTCX1) X2.2
XTAL_PCH_RTC2: C208.1 R151.2 WBG1.R47(RTCX2) X2.1

Not connected (* = marked no-connect by the designer): WBG1 AG9(NCTF/TP#AG9)* AG10(NCTF/TP#AG10)* AW6(RESERVED#AW6)* AW7(NCTF/TP#AW7)* B4(NC_DUT_DETECT_1)* BA6(RESERVED#BA6)* BA7(NCTF/TP#BA7)* BA18(CLKOUT_GPB_PCIE_P1)* BA34(NCTF/TP#BA34)* BB2(CLKOUT_PCIE_N6)* BB4(CLKOUT_PCIE_P6)* BC7(NCTF/TP#BC7)* BC11(CLKOUT_PCIE_N7)* BC18(CLKOUT_GPB_PCIE_N1)* BC21(CLKOUT_PCIE_P0)* BC34(NCTF/TP#BC34)* BD7(NCTF/TP#BD7)* BD11(CLKOUT_PCIE_P7)* BD21(CLKOUT_PCIE_N0)* BF2(NC_DUT_DETECT_2)* BF6(CLKOUT_PCIE_N5)* BF8(CLKOUT_PCIE_N4)* BF10(CLKOUT_PCIE_N1)* BF12(CLKOUT_GPB_PCIE_N0)* BF14(CLKOUT_PCIE_N3)* BF16(CLKOUT_PCIE_N2)* BF20(CLKOUT_GPB_PCIE_N2)* BH5(CLKOUT_PCIE_P5)* BH8(CLKOUT_PCIE_P4)* BH10(CLKOUT_PCIE_P1)* BH12(CLKOUT_GPB_PCIE_P0)* BH14(CLKOUT_PCIE_P3)* BH16(CLKOUT_PCIE_P2)* BH20(CLKOUT_GPB_PCIE_P2)* BH45(NCTF/TP#BH45)* BH46(NC_DUT_DETECT_3)* BJ45(NCTF/TP#BJ45)* N14(NCTF/TP#N14)* N15(NCTF/TP#N15)* N49(NCTF/TP#N49)* V6(NCTF/TP#V6)* V7(NCTF/TP#V7)* V35(PWM1)* V38(PWM0)* V40(PWM2)* V43(PWM3)*

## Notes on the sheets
sheet 87
- WELLSBURG - POWER
- DESIGN NOTE:
  1.0V OR 1.05V (NOMINAL) SUPPLY
  NOT FILTERED :
  STUFF: R155
  DO NOT STUFF: R154
  FILTERED (DEFAULT)
  STUFF: R154
  DO NOT STUFF: R155
- DMI PLL FILTER
- 1.05V PCIE/DMI $SECTION
- CAD NOTE:
  PLACE CAP
  BOARDCAP STYLE
  NEAR TO PIN
  VCCADMIPLL_1P5
- SATA PLL FILTER
- CAD NOTE:
  1.05 V FOR VRM BYPASS MODE (FILT REQUIRED)
  1.5V WHEN USING INTERNAL VRM (NO FILT REQUIRED)
  THIS POWER IS SUPPLIED WITH CORE WELL.
- ROOM=WBG_FILTERING
- P1V05_XCK_VRM - CLOCK INTEGRATION
- FAB1 REV013 20150413
- Change to 63.00000.00L
- DE NOTE:
  OPTION TO POWER
  PCH FUSE WITH
  OTHER VOLTAGE
- DESIGN NOTE:
   1.5V WHEN USING INTERNAL VRM
  (NO FILTERING REQUIRED) DEFAULT
  STUFF: R3H63,R3F45,R3H57,R3F50
  DO NOT STUFF: R3H64,R3F46,R3H56,R3F51
- DESIGN NOTE:
  1.05 V FOR VRM BYPASS MODE (FILT REQUIRED)
  1.5V WHEN USING INTERNAL VRM (NO FILT REQUIRED)
  THIS POWER IS SUPPLIED WITH CORE WELL.
- FAB1 REV025 20150504
- 1.05 V FOR VRM BYPASS MODE
  (FILTERING REQUIRED)
  STUFF: R3H64,R3F46,R3H56,R3F51
  DO NOT STUFF: R3H63,R3F45,R3H57,R3F50
- USB3 PLL FILTER
- FAB1 REV005 20150322
- DESIGN NOTE:
  1.05 V FOR VRM BYPASS MODE (FILT REQUIRED)
  1.5V WHEN USING INTERNAL VRM (NO FILT REQUIRED)
  THIS POWER IS SUPPLIED WITH CORE WELL.
- CAD NOTE:
  PLACE CAP
  BSC STYLE
  NEAR TO PIN
  VCCDSW3_3
- Place C221 close to WBG1.AP36
- SATAX PLL FILTER
- P1V05_XCK_DCB - CLOCK INTEGRATION
- FAB1 REV005 20150322
- DESIGN NOTE:
  FC RW10: REMOVE THE INDUCTOR AND
  REPLACE WITH RES A93552-002
  EMPTY CAP 10UF
- CAD NOTE:
  PLACE CAP
  (E) STYLE
  NEAR TO PIN
  VCCAXCK_DCB_1P05
- CAD NOTE:
  1.05 V FOR VRM BYPASS MODE (FILT REQUIRED)
  1.5V WHEN USING INTERNAL VRM (NO FILT REQUIRED)
  THIS POWER IS SUPPLIED WITH CORE WELL.
- ALLOWS FOR BYPASS OPTION WITH DISCRETE CAP.
sheet 88
- WELLSBURG - CLOCK
- DESIGN NOTE:
  * DESIGN NOTE: UNSTUFF 0 OHMS RESISTOR FOR EXTCLK.
  * S01 = STUFFING OPTION
  EXTERNAL (S01 = STUFF) (S0 = UNSTUFF)
- INTEL
- Place close to R407
- FROM WBG iCLK
- TO DB1900Z
- INTEL
- EVT 20150127
- Place close to R412
- INTEL
- GPIO67 - When configured as GPIO, default direction is
  Output (GPO).
- FAB1 20150303
- Pls see to ensure how to Configurable
  as a GPIO or as a programmable output clock.
- FAB1 REV012 20150409
- ¡E  Short (< than 1.25¡¨) shielded traces on XTAL_P/XTAL_N to minimize cross-talk
      induced jitter
  ¡E  Shield XTAL_P/XTAL_N signals and reference to ground planes
  ¡E  Recommended to not route high frequency signals directly below the crystal.
  ¡E  Maintain adequate spacing between adjacent signals and XTAL_P/XTAL_N signals
sheet 89
- WELLSBURG - SPI
- FAB1 REV025 20150504
- FAB1 REV025 20150502
- Remove test points
- NOTE:
  NOT FOR EDS.
  THESE PINS ARE NOT VISIBLE TO THE CUSTOMER
sheet 90
- WELLSBURG - GPIO & SMB
- TO BMC & CPLD
- TO WBG & CPLD
- PCH Integrates 20 k nominal pull-up
  resistors on these signal lines.
- FAB1 REV005 20150322
- FAB1 REV004 20150320
- FAB1 REV005 20150322
- LAN PHY Power Control: LAN_PHY_PWR_CTRL
  should be connected to LAN_DISABLE_N on the PHY.
  PCH will drive LAN_PHY_PWR_CTRL low to put the
  PHY into a low power state when functionality is
  not needed.
- Notes:
  1. LAN_PHY_PWR_CTRL can only be driven low
     if SLP_LAN# is deasserted.
  2. Signal can instead be used as GPIO12.
- FAB1 REV004 20150320
- WBG P.90
- Connect to Mezz. PCIE0 and BMC
- PDG P.526
- Min. Ven high for TPS53312 = 2V
- Max. Ven low for TPS53312  = 0.4V
- SUSACK# is only required to change
  in response to SUSWARN# if Deep
  Sx is supported by the platform.
- POP R287
- ME(M3) IN STBY
- PDG P.504
- POP R288
- ME IN S0 ONLY
- FAB1 REV005 20150320
- 63.10633.15L
- PDG P.368
- DESIGN NOTE:
  MANTAIN 0603 PACKAGE FOR
  1 MOHM AND 10 MOHM RESISTORS.
- DESIGN NOTE:
  PDG RECOMMENDED COMPONENTS
  AND VALUE.
  CAP VALUE MAY NEED TUNING.
- FAB1 REV013 20150413
- Change to 63.R0034.1DL
sheet 91
- WELLSBURG - SATA
- Place cap. close to chip within 0.5 inch.
- TO SATA CONNECTORS
- TO minSAS-HDX4 port1
- TO minSAS-HDX4 port1
- FAB1 REV003 20150318
- DESIGN NOTE:
  TERMINATING UNUSED 1-WIRE BUS TO GND
- FAB1 REV025 20150504
- power management sync
- PDG P.235
- INPUTS
- OUTPUT
- CAD NOTE: PLACE RESISTORS AS CLOSE AS POSSIBLE TO PCH
- FAB1 REV021 20150424
- If unused, requires 8.2k to 10k pull-up
  resistorsto P3V3 or ground.
- A
- B
- Y
- H
- H
- H(Z)
- L
- X
- L
- X
- L
- L
- FAB1 REV003 20150318
- OD pin,an external pull-up of 4.7k to 10k to
  P3V3 is required.
